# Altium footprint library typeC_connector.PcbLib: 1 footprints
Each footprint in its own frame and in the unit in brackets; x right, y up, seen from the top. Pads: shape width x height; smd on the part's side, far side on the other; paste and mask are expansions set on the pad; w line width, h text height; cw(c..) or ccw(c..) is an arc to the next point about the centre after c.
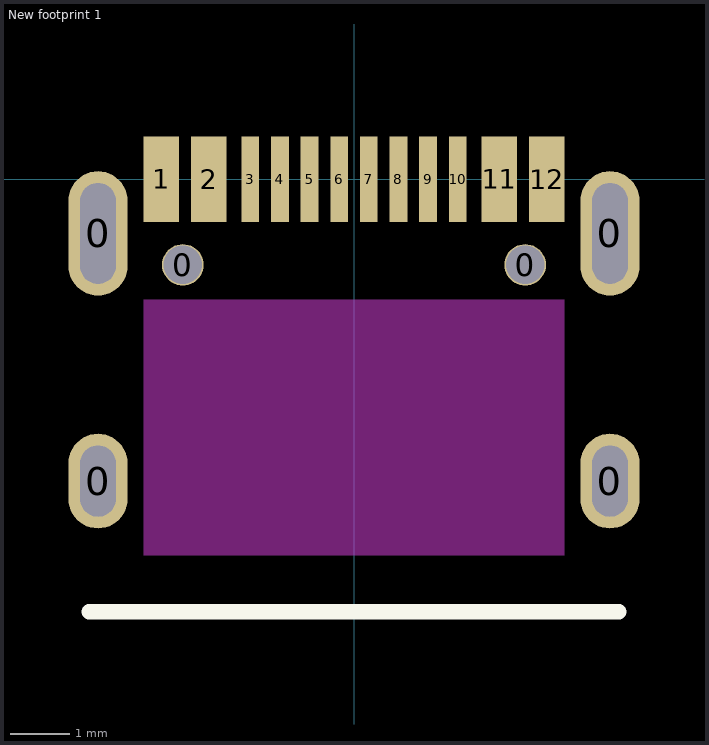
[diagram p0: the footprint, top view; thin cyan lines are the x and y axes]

## New footprint 1 [mm]
pads (18):
  rrect100% 1x1.6 hole 1.2 slot 0.6 at 0 deg: 0(-4.32,-5.095) 0(4.32,-5.095)
  rrect100% 1x2.1 hole 1.7 slot 0.6 at 0 deg: 0(-4.32,-0.915) 0(4.32,-0.915)
  round 0.7 hole 0.65: 0(-2.89,-1.445) 0(2.89,-1.445)
  rect 0.6x1.45 smd: 1(-3.25,0) 2(-2.45,0) 11(2.45,0) 12(3.25,0)
  rect 0.3x1.45 smd: 3(-1.75,0) 4(-1.25,0) 5(-0.75,0) 6(-0.25,0) 7(0.25,0) 8(0.75,0) 9(1.25,0) 10(1.75,0)
Top Overlay:
  lines w0.254: -4.47,-7.3 4.47,-7.3
Keep-Out Layer:
  rectangle: -3.556,-6.35 3.556,-2.032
